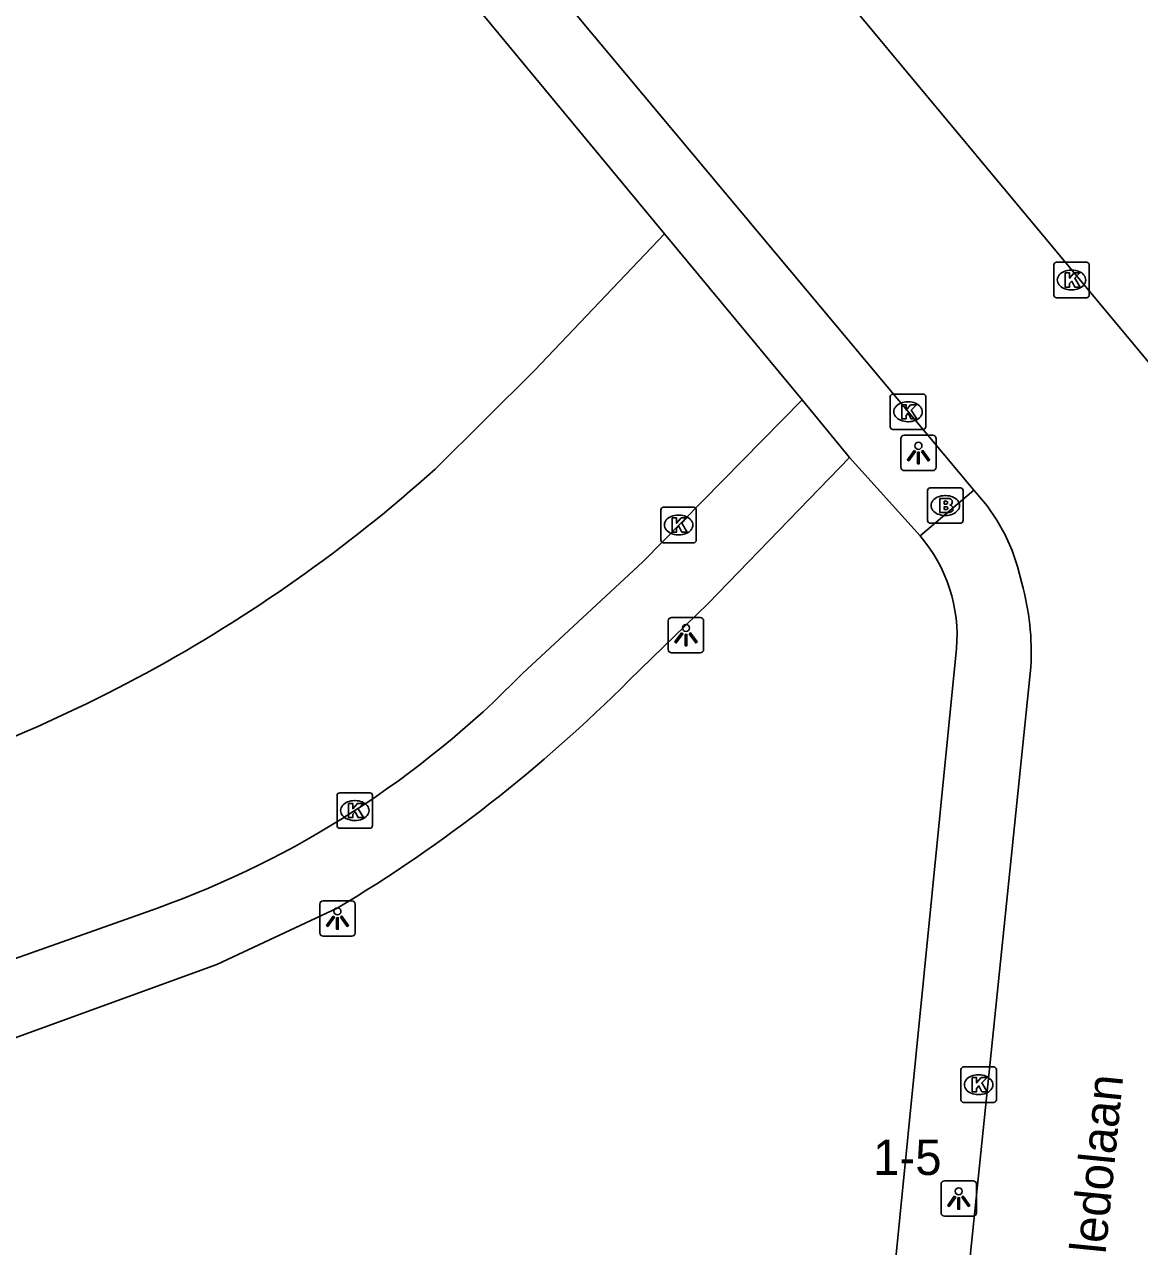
# Model space of a CAD drawing. Extents: x 159451 to 160663, y 388402 to 389723.
# Drawn here: x 159708.67 to 159740.16, y 389036.93 to 389071.41 of the extents above; entities that cross this region are included whole.
import ezdxf

# ---------------------------------------------------------------- set-up
doc = ezdxf.new("R2010")
doc.units = 0
for name, color, linetype in [('IMGEO_Brandkraan', 7, 'Continuous'), ('IMGEO_Kolk', 7, 'Continuous'), ('IMGEO_Lichtpunt', 7, 'Continuous'), ('IMGEO_Openbare_ruimte_label', 7, 'Continuous'), ('IMGEO_Pand_nummerreeks', 7, 'Continuous'), ('IMGEO_Rijbaan_lokaal_open', 7, 'Continuous'), ('IMGEO_Voetpad_open', 7, 'Continuous')]:
    doc.layers.add(name, color=color, linetype=linetype)

msp = doc.modelspace()

# ---------------------------------------------------------------- linework, layer by layer
at = {"layer": 'IMGEO_Brandkraan'}
for p, q in [((159734.244, 389058.339), (159735.096, 389058.339)), ((159734.169, 389057.413), (159734.169, 389058.265)), ((159734.657, 389058.119), (159734.682, 389058.119)), ((159735.17, 389058.265), (159735.17, 389057.413)), ((159735.096, 389057.339), (159734.244, 389057.339)), ((159734.68, 389057.559), (159734.655, 389057.559))]:
    msp.add_line(p, q, dxfattribs=at)
for points in [[(159734.244, 389058.339), (159735.096, 389058.339)], [(159734.169, 389057.413), (159734.169, 389058.265)], [(159734.517, 389058.039), (159734.517, 389057.639), (159734.73, 389057.639)], [(159734.748, 389058.039), (159734.517, 389058.039)], [(159735.17, 389058.265), (159735.17, 389057.413)], [(159734.696, 389057.958), (159734.642, 389057.958), (159734.642, 389057.882)], [(159734.642, 389057.882), (159734.695, 389057.882)], [(159734.704, 389057.806), (159734.642, 389057.806), (159734.642, 389057.725)], [(159734.642, 389057.725), (159734.704, 389057.725)], [(159735.096, 389057.339), (159734.244, 389057.339)]]:
    msp.add_lwpolyline(points, dxfattribs=at)
for centre, radius, start, end in [((159734.246, 389058.263), 0.0765, 91.552, 178.448), ((159734.246, 389058.263), 0.0765, 91.552, 178.448), ((159735.094, 389058.263), 0.0765, 1.552, 88.448), ((159735.094, 389058.263), 0.0765, 1.552, 88.448), ((159734.752, 389057.894), 0.145, 59.4692, 91.5367), ((159734.777, 389057.941), 0.0922, 285.5137, 58.1501), ((159734.697, 389057.92), 0.0379, 267.8285, 90.9355), ((159734.705, 389057.765), 0.0404, 269.8759, 90.5077), ((159734.736, 389057.89), 0.251, 268.6676, 293.5347), ((159734.782, 389057.749), 0.105, 301.3115, 78.989), ((159734.246, 389057.415), 0.0765, 181.552, 268.448), ((159734.246, 389057.415), 0.0765, 181.552, 268.448), ((159735.094, 389057.415), 0.0765, 271.552, 358.448), ((159735.094, 389057.415), 0.0765, 271.552, 358.448)]:
    msp.add_arc(centre, radius, start, end, dxfattribs=at)
for centre, major_axis, ratio, start_param, end_param in [((159734.656, 389057.839), (-0.387, 0.002), 0.722429, 4.712389, 7.853982), ((159734.681, 389057.839), (-0.39, 0.002), 0.717154, 1.570796, 4.712389)]:
    msp.add_ellipse(centre, major_axis=major_axis, ratio=ratio, start_param=start_param, end_param=end_param, dxfattribs=at)
at = {"layer": 'IMGEO_Kolk'}
for p, q in [((159737.733, 389063.778), (159737.733, 389064.63)), ((159737.808, 389064.704), (159738.66, 389064.704)), ((159738.734, 389064.63), (159738.734, 389063.778)), ((159738.221, 389064.484), (159738.246, 389064.484)), ((159738.244, 389063.924), (159738.219, 389063.924)), ((159738.66, 389063.704), (159737.808, 389063.704)), ((159733.117, 389060.059), (159733.117, 389060.911)), ((159733.192, 389060.985), (159734.044, 389060.985)), ((159733.605, 389060.765), (159733.63, 389060.765)), ((159734.118, 389060.911), (159734.118, 389060.059)), ((159733.628, 389060.205), (159733.603, 389060.205)), ((159734.044, 389059.985), (159733.192, 389059.985)), ((159726.638, 389056.864), (159726.638, 389057.716)), ((159726.713, 389057.79), (159727.565, 389057.79)), ((159727.639, 389057.716), (159727.639, 389056.864)), ((159727.126, 389057.57), (159727.151, 389057.57)), ((159727.149, 389057.01), (159727.124, 389057.01)), ((159727.565, 389056.79), (159726.713, 389056.79)), ((159717.571, 389049.732), (159718.423, 389049.732)), ((159717.496, 389048.806), (159717.496, 389049.658)), ((159717.984, 389049.512), (159718.009, 389049.512)), ((159718.497, 389049.658), (159718.497, 389048.806)), ((159718.423, 389048.732), (159717.571, 389048.732)), ((159718.007, 389048.952), (159717.982, 389048.952)), ((159735.11, 389041.069), (159735.11, 389041.921)), ((159735.185, 389041.995), (159736.037, 389041.995)), ((159735.598, 389041.775), (159735.623, 389041.775)), ((159736.111, 389041.921), (159736.111, 389041.069)), ((159735.621, 389041.215), (159735.596, 389041.215)), ((159736.037, 389040.995), (159735.185, 389040.995))]:
    msp.add_line(p, q, dxfattribs=at)
for points in [[(159737.733, 389063.778), (159737.733, 389064.63)], [(159737.808, 389064.704), (159738.66, 389064.704)], [(159738.734, 389064.63), (159738.734, 389063.778)], [(159738.054, 389064.404), (159738.177, 389064.404), (159738.177, 389064.253), (159738.307, 389064.404), (159738.471, 389064.404), (159738.325, 389064.253), (159738.478, 389064.004), (159738.326, 389064.004), (159738.241, 389064.168), (159738.177, 389064.101), (159738.177, 389064.004), (159738.054, 389064.004), (159738.054, 389064.404)], [(159738.66, 389063.704), (159737.808, 389063.704)], [(159733.117, 389060.059), (159733.117, 389060.911)], [(159733.192, 389060.985), (159734.044, 389060.985)], [(159734.118, 389060.911), (159734.118, 389060.059)], [(159733.438, 389060.685), (159733.561, 389060.685), (159733.561, 389060.534), (159733.691, 389060.685), (159733.855, 389060.685), (159733.709, 389060.534), (159733.862, 389060.285), (159733.71, 389060.285), (159733.625, 389060.449), (159733.561, 389060.382), (159733.561, 389060.285), (159733.438, 389060.285), (159733.438, 389060.685)], [(159734.044, 389059.985), (159733.192, 389059.985)], [(159726.638, 389056.864), (159726.638, 389057.716)], [(159726.713, 389057.79), (159727.565, 389057.79)], [(159727.639, 389057.716), (159727.639, 389056.864)], [(159726.959, 389057.49), (159727.082, 389057.49), (159727.082, 389057.339), (159727.212, 389057.49), (159727.376, 389057.49), (159727.23, 389057.339), (159727.383, 389057.09), (159727.231, 389057.09), (159727.146, 389057.254), (159727.082, 389057.187), (159727.082, 389057.09), (159726.959, 389057.09), (159726.959, 389057.49)], [(159727.565, 389056.79), (159726.713, 389056.79)], [(159717.571, 389049.732), (159718.423, 389049.732)], [(159717.496, 389048.806), (159717.496, 389049.658)], [(159717.817, 389049.432), (159717.94, 389049.432), (159717.94, 389049.281), (159718.07, 389049.432), (159718.234, 389049.432), (159718.088, 389049.281), (159718.241, 389049.032), (159718.089, 389049.032), (159718.004, 389049.196), (159717.94, 389049.129), (159717.94, 389049.032), (159717.817, 389049.032), (159717.817, 389049.432)], [(159718.497, 389049.658), (159718.497, 389048.806)], [(159718.423, 389048.732), (159717.571, 389048.732)], [(159735.11, 389041.069), (159735.11, 389041.921)], [(159735.185, 389041.995), (159736.037, 389041.995)], [(159736.111, 389041.921), (159736.111, 389041.069)], [(159735.431, 389041.695), (159735.554, 389041.695), (159735.554, 389041.544), (159735.684, 389041.695), (159735.848, 389041.695), (159735.702, 389041.544), (159735.855, 389041.295), (159735.703, 389041.295), (159735.618, 389041.459), (159735.554, 389041.392), (159735.554, 389041.295), (159735.431, 389041.295), (159735.431, 389041.695)], [(159736.037, 389040.995), (159735.185, 389040.995)]]:
    msp.add_lwpolyline(points, dxfattribs=at)
for centre, start, end in [((159737.81, 389064.628), 91.552, 178.448), ((159737.81, 389064.628), 91.552, 178.448), ((159738.658, 389064.628), 1.552, 88.448), ((159738.658, 389064.628), 1.552, 88.448), ((159737.81, 389063.78), 181.552, 268.448), ((159737.81, 389063.78), 181.552, 268.448), ((159738.658, 389063.78), 271.552, 358.448), ((159738.658, 389063.78), 271.552, 358.448), ((159733.194, 389060.909), 91.552, 178.448), ((159733.194, 389060.909), 91.552, 178.448), ((159734.042, 389060.909), 1.552, 88.448), ((159734.042, 389060.909), 1.552, 88.448), ((159733.194, 389060.061), 181.552, 268.448), ((159733.194, 389060.061), 181.552, 268.448), ((159734.042, 389060.061), 271.552, 358.448), ((159734.042, 389060.061), 271.552, 358.448), ((159726.715, 389057.714), 91.552, 178.448), ((159726.715, 389057.714), 91.552, 178.448), ((159727.563, 389057.714), 1.552, 88.448), ((159727.563, 389057.714), 1.552, 88.448), ((159726.715, 389056.866), 181.552, 268.448), ((159726.715, 389056.866), 181.552, 268.448), ((159727.563, 389056.866), 271.552, 358.448), ((159727.563, 389056.866), 271.552, 358.448), ((159717.573, 389049.656), 91.552, 178.448), ((159717.573, 389049.656), 91.552, 178.448), ((159718.421, 389049.656), 1.552, 88.448), ((159718.421, 389049.656), 1.552, 88.448), ((159717.573, 389048.808), 181.552, 268.448), ((159717.573, 389048.808), 181.552, 268.448), ((159718.421, 389048.808), 271.552, 358.448), ((159718.421, 389048.808), 271.552, 358.448), ((159735.187, 389041.919), 91.552, 178.448), ((159735.187, 389041.919), 91.552, 178.448), ((159736.035, 389041.919), 1.552, 88.448), ((159736.035, 389041.919), 1.552, 88.448), ((159735.187, 389041.071), 181.552, 268.448), ((159735.187, 389041.071), 181.552, 268.448), ((159736.035, 389041.071), 271.552, 358.448), ((159736.035, 389041.071), 271.552, 358.448)]:
    msp.add_arc(centre, 0.0765, start, end, dxfattribs=at)
for centre, major_axis, ratio, start_param, end_param in [((159738.22, 389064.204), (-0.387, 0.002), 0.722429, 4.712389, 7.853982), ((159738.245, 389064.204), (-0.39, 0.002), 0.717154, 1.570796, 4.712389), ((159733.604, 389060.485), (-0.387, 0.002), 0.722429, 4.712389, 7.853982), ((159733.629, 389060.485), (-0.39, 0.002), 0.717154, 1.570796, 4.712389), ((159727.125, 389057.29), (-0.387, 0.002), 0.722429, 4.712389, 7.853982), ((159727.15, 389057.29), (-0.39, 0.002), 0.717154, 1.570796, 4.712389), ((159717.983, 389049.232), (-0.387, 0.002), 0.722429, 4.712389, 7.853982), ((159718.008, 389049.232), (-0.39, 0.002), 0.717154, 1.570796, 4.712389), ((159735.597, 389041.495), (-0.387, 0.002), 0.722429, 4.712389, 7.853982), ((159735.622, 389041.495), (-0.39, 0.002), 0.717154, 1.570796, 4.712389)]:
    msp.add_ellipse(centre, major_axis=major_axis, ratio=ratio, start_param=start_param, end_param=end_param, dxfattribs=at)
at = {"layer": 'IMGEO_Lichtpunt'}
for p, q in [((159733.413, 389059.726), (159733.413, 389058.919)), ((159733.413, 389059.726), (159733.413, 389058.919)), ((159734.315, 389059.821), (159733.507, 389059.821)), ((159734.315, 389059.821), (159733.507, 389059.821)), ((159734.409, 389058.919), (159734.409, 389059.726)), ((159734.409, 389058.919), (159734.409, 389059.726)), ((159733.507, 389058.825), (159734.315, 389058.825)), ((159733.507, 389058.825), (159734.315, 389058.825)), ((159726.849, 389054.587), (159726.849, 389053.78)), ((159726.849, 389054.587), (159726.849, 389053.78)), ((159727.751, 389054.682), (159726.943, 389054.682)), ((159727.751, 389054.682), (159726.943, 389054.682)), ((159727.845, 389053.78), (159727.845, 389054.587)), ((159727.845, 389053.78), (159727.845, 389054.587)), ((159726.943, 389053.686), (159727.751, 389053.686)), ((159726.943, 389053.686), (159727.751, 389053.686)), ((159717.008, 389046.589), (159717.008, 389045.782)), ((159717.008, 389046.589), (159717.008, 389045.782)), ((159717.91, 389046.684), (159717.102, 389046.684)), ((159717.91, 389046.684), (159717.102, 389046.684)), ((159718.004, 389045.782), (159718.004, 389046.589)), ((159718.004, 389045.782), (159718.004, 389046.589)), ((159717.102, 389045.688), (159717.91, 389045.688)), ((159717.102, 389045.688), (159717.91, 389045.688)), ((159734.55, 389038.689), (159734.55, 389037.882)), ((159734.55, 389038.689), (159734.55, 389037.882)), ((159735.452, 389038.784), (159734.644, 389038.784)), ((159735.452, 389038.784), (159734.644, 389038.784)), ((159735.546, 389037.882), (159735.546, 389038.689)), ((159735.546, 389037.882), (159735.546, 389038.689)), ((159734.644, 389037.788), (159735.452, 389037.788)), ((159734.644, 389037.788), (159735.452, 389037.788))]:
    msp.add_line(p, q, dxfattribs=at)
for points in [[(159733.787, 389059.39), (159733.826, 389059.362), (159733.638, 389059.1), (159733.6, 389059.127), (159733.787, 389059.39)], [(159733.889, 389059.342), (159733.936, 389059.342), (159733.936, 389059.02), (159733.889, 389059.02), (159733.889, 389059.342)], [(159733.999, 389059.362), (159734.037, 389059.389), (159734.224, 389059.127), (159734.185, 389059.099), (159733.999, 389059.362)], [(159727.223, 389054.251), (159727.262, 389054.223), (159727.074, 389053.961), (159727.036, 389053.988), (159727.223, 389054.251)], [(159727.325, 389054.203), (159727.372, 389054.203), (159727.372, 389053.881), (159727.325, 389053.881), (159727.325, 389054.203)], [(159727.435, 389054.223), (159727.473, 389054.25), (159727.66, 389053.988), (159727.621, 389053.96), (159727.435, 389054.223)], [(159717.382, 389046.253), (159717.421, 389046.225), (159717.233, 389045.963), (159717.195, 389045.99), (159717.382, 389046.253)], [(159717.594, 389046.225), (159717.632, 389046.252), (159717.819, 389045.99), (159717.78, 389045.962), (159717.594, 389046.225)], [(159717.484, 389046.205), (159717.531, 389046.205), (159717.531, 389045.883), (159717.484, 389045.883), (159717.484, 389046.205)], [(159734.924, 389038.353), (159734.963, 389038.325), (159734.775, 389038.063), (159734.737, 389038.09), (159734.924, 389038.353)], [(159735.026, 389038.305), (159735.073, 389038.305), (159735.073, 389037.983), (159735.026, 389037.983), (159735.026, 389038.305)], [(159735.136, 389038.325), (159735.174, 389038.352), (159735.361, 389038.09), (159735.322, 389038.062), (159735.136, 389038.325)]]:
    msp.add_lwpolyline(points, dxfattribs=at)
for centre in [(159733.912, 389059.524), (159727.348, 389054.385), (159717.507, 389046.387), (159735.049, 389038.487)]:
    msp.add_circle(centre, 0.0994, dxfattribs=at)
for centre, start, end in [((159733.507, 389059.726), 90, 180), ((159733.507, 389059.726), 90, 180), ((159734.315, 389059.726), 0, 90), ((159734.315, 389059.726), 0, 90), ((159733.507, 389058.919), 180, 270), ((159733.507, 389058.919), 180, 270), ((159734.315, 389058.919), 270, 0), ((159734.315, 389058.919), 270, 360), ((159726.943, 389054.587), 90, 180), ((159726.943, 389054.587), 90, 180), ((159727.751, 389054.587), 0, 90), ((159727.751, 389054.587), 0, 90), ((159726.943, 389053.78), 180, 270), ((159726.943, 389053.78), 180, 270), ((159727.751, 389053.78), 270, 0), ((159727.751, 389053.78), 270, 360), ((159717.102, 389046.589), 90, 180), ((159717.102, 389046.589), 90, 180), ((159717.91, 389046.589), 0, 90), ((159717.91, 389046.589), 0, 90), ((159717.102, 389045.782), 180, 270), ((159717.102, 389045.782), 180, 270), ((159717.91, 389045.782), 270, 0), ((159717.91, 389045.782), 270, 360), ((159734.644, 389038.689), 90, 180), ((159734.644, 389038.689), 90, 180), ((159735.452, 389038.689), 0, 90), ((159735.452, 389038.689), 0, 90), ((159734.644, 389037.882), 180, 270), ((159734.644, 389037.882), 180, 270), ((159735.452, 389037.882), 270, 0), ((159735.452, 389037.882), 270, 360)]:
    msp.add_arc(centre, 0.0946, start, end, dxfattribs=at)
at = {"layer": 'IMGEO_Rijbaan_lokaal_open'}
for points in [[(159735.475, 389058.272), (159729.843, 389064.997), (159708.515, 389090.5), (159705.801, 389093.82), (159694.035, 389108.156), (159691.92, 389110.497), (159688.727, 389114.585), (159685.913, 389118.942), (159682.577, 389125.009)], [(159722.021, 389006.481), (159736.552, 389017.776), (159737.694, 389018.927), (159738.949, 389020.892), (159739.859, 389023.068), (159740.22, 389024.649), (159743.132, 389053.016), (159743.13, 389055.644), (159742.318, 389058.742), (159740.742, 389061.477), (159712.143, 389095.814)], [(159726.74, 389065.51), (159723.067, 389061.645), (159720.262, 389058.863)], [(159726.74, 389065.51), (159730.625, 389060.817)], [(159722.729, 389053.098), (159726.131, 389056.253), (159730.625, 389060.817)], [(159736.827, 389055.651), (159736.712, 389056.117), (159736.555, 389056.572), (159736.358, 389057.01), (159736.122, 389057.43), (159735.85, 389057.826), (159735.544, 389058.197), (159735.475, 389058.272)], [(159734.226, 389025.499), (159737.083, 389053.28)], [(159668.491, 389029.41), (159676.353, 389032.432), (159691.434, 389038.813), (159697.167, 389041.076), (159712.428, 389046.481)]]:
    msp.add_lwpolyline(points, dxfattribs=at)
for centre, radius, start, end in [((159691.72, 389090.679), 42.742, 285.0751, 311.8944), ((159729.982, 389053.713), 7.114, 356.5141, 15.8107), ((159703.19, 389072.189), 27.318, 289.766, 315.6646)]:
    msp.add_arc(centre, radius, start, end, dxfattribs=at)
at = {"layer": 'IMGEO_Voetpad_open'}
for points in [[(159700.795, 389096.787), (159703.16, 389093.947), (159726.74, 389065.51)], [(159730.625, 389060.817), (159731.964, 389059.199)], [(159725.746, 389052.911), (159727.978, 389055.076), (159731.964, 389059.199)], [(159731.964, 389059.199), (159733.958, 389056.98)], [(159733.958, 389056.98), (159735.475, 389058.272)], [(159734.987, 389053.802), (159732.25, 389026.319)], [(159687.227, 389034.723), (159691.615, 389036.62), (159696.858, 389038.718), (159702.65, 389040.726), (159714.104, 389044.886), (159717.499, 389046.477)]]:
    msp.add_lwpolyline(points, dxfattribs=at)
for centre, radius, start, end in [((159730.668, 389054.159), 4.334, 355.2716, 40.6111), ((159695.803, 389082.789), 42.3, 300.8579, 315.0621)]:
    msp.add_arc(centre, radius, start, end, dxfattribs=at)

# ---------------------------------------------------------------- texts
at = {"layer": 'IMGEO_Openbare_ruimte_label'}
msp.add_text('Toledolaan', height=1, rotation=84.3179, dxfattribs=at).set_placement((159739.039, 389035.148))
at = {"layer": 'IMGEO_Pand_nummerreeks'}
msp.add_text('1-5', height=1, dxfattribs=at).set_placement((159732.632, 389038.948))

doc.saveas('drawing.dxf')
